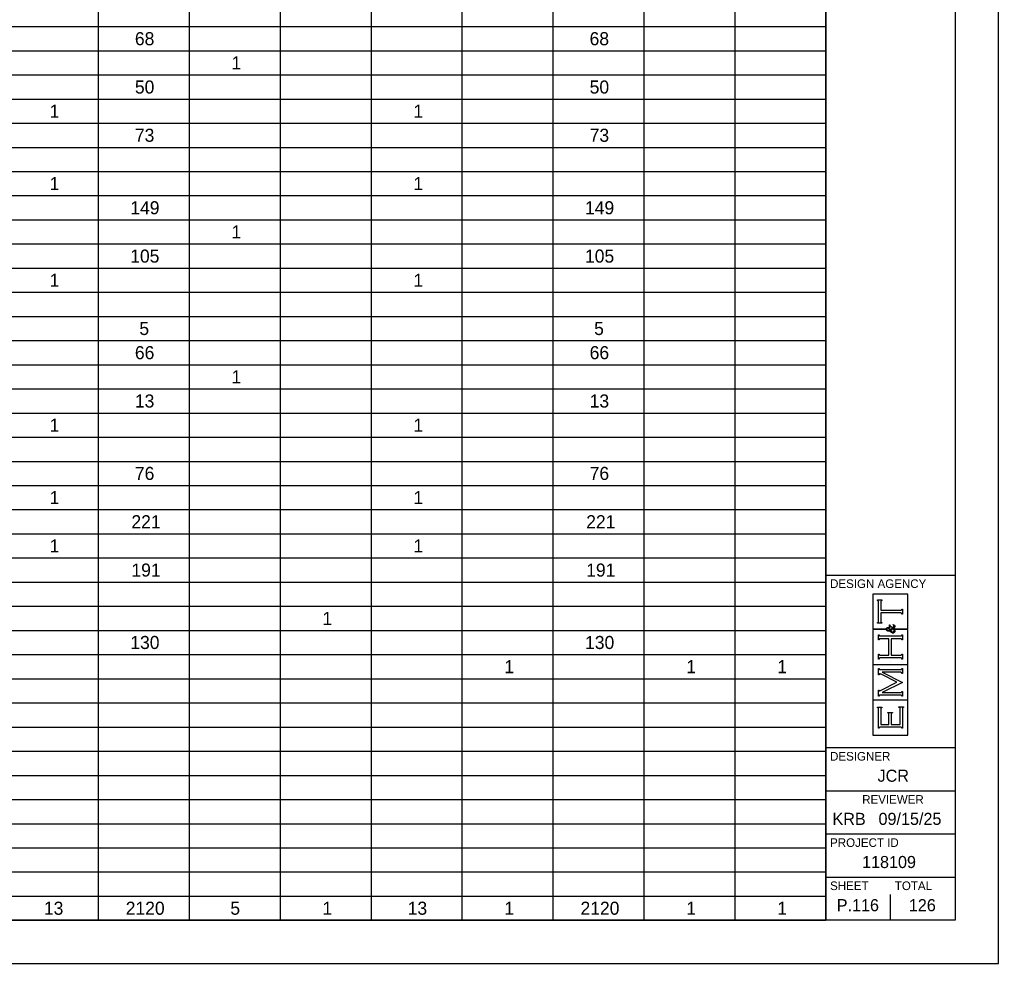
# Model space of a CAD drawing. Extents: x 0 to 34, y 0 to 22.
# Drawn here: x 22.66 to 34, y 0 to 10.94 of the extents above; entities that cross this region are included whole.
import ezdxf

# ---------------------------------------------------------------- set-up
doc = ezdxf.new("R2010")
doc.units = 0
for name, color, linetype in [('Default', 7, 'Continuous'), ('SH_Border', 7, 'Continuous'), ('SH_Cut_Line', 7, 'Continuous'), ('SH_Data', 7, 'Continuous')]:
    doc.layers.add(name, color=color, linetype=linetype)

msp = doc.modelspace()

# ---------------------------------------------------------------- linework, layer by layer
at = {"layer": 'Default'}
for p, q in [((23.571, 21.489), (23.571, 0.5)), ((24.625, 21.489), (24.625, 0.5)), ((25.679, 21.489), (25.679, 0.5)), ((26.732, 21.489), (26.732, 0.5)), ((27.786, 21.489), (27.786, 0.5)), ((28.839, 21.489), (28.839, 0.5)), ((29.893, 21.489), (29.893, 0.5)), ((30.946, 21.489), (30.946, 0.5)), ((32, 21.489), (32, 0.5)), ((1.496, 10.855), (32, 10.855)), ((1.496, 10.575), (32, 10.575)), ((1.496, 10.295), (32, 10.295)), ((1.496, 10.015), (32, 10.015)), ((1.496, 9.735), (32, 9.735)), ((1.496, 9.455), (32, 9.455)), ((1.496, 9.175), (32, 9.175)), ((1.496, 8.896), (32, 8.896)), ((1.496, 8.616), (32, 8.616)), ((1.496, 8.336), (32, 8.336)), ((1.496, 8.056), (32, 8.056)), ((1.496, 7.776), (32, 7.776)), ((1.496, 7.496), (32, 7.496)), ((1.496, 7.217), (32, 7.217)), ((1.496, 6.937), (32, 6.937)), ((1.496, 6.657), (32, 6.657)), ((1.496, 6.377), (32, 6.377)), ((1.496, 6.097), (32, 6.097)), ((1.496, 5.817), (32, 5.817)), ((1.496, 5.537), (32, 5.537)), ((1.496, 5.258), (32, 5.258)), ((1.496, 4.978), (32, 4.978)), ((1.496, 4.698), (32, 4.698)), ((1.496, 4.418), (32, 4.418)), ((1.496, 4.138), (32, 4.138)), ((1.496, 3.858), (32, 3.858)), ((1.496, 3.578), (32, 3.578)), ((1.496, 3.299), (32, 3.299)), ((1.496, 3.019), (32, 3.019)), ((1.496, 2.739), (32, 2.739)), ((1.496, 2.459), (32, 2.459)), ((1.496, 2.179), (32, 2.179)), ((1.496, 1.899), (32, 1.899)), ((1.496, 1.619), (32, 1.619)), ((1.496, 1.34), (32, 1.34)), ((1.496, 1.06), (32, 1.06)), ((1.496, 0.78), (32, 0.78)), ((1.496, 0.5), (32, 0.5))]:
    msp.add_line(p, q, dxfattribs=at)
at = {"layer": 'SH_Border'}
for p, q in [((32, 0.5), (32, 21.5)), ((32, 4.5), (33.5, 4.5)), ((32, 2.5), (33.5, 2.5)), ((32, 2), (33.5, 2)), ((32, 1.5), (33.5, 1.5)), ((32, 1), (33.5, 1))]:
    msp.add_line(p, q, dxfattribs=at)
msp.add_lwpolyline([(1.5, 21.5), (33.5, 21.5), (33.5, 0.5), (1.5, 0.5)], close=True, dxfattribs=at)
at = {"layer": 'SH_Cut_Line'}
msp.add_lwpolyline([(0, 0), (34, 0), (34, 22), (0, 22)], close=True, dxfattribs=at)
at = {"layer": 'SH_Data'}
for p, q in [((32.952, 4.279), (32.547, 4.279)), ((32.547, 4.279), (32.547, 3.875)), ((32.598, 4.204), (32.598, 4.211)), ((32.598, 4.211), (32.65, 4.211)), ((32.603, 4.203), (32.598, 4.204)), ((32.606, 4.201), (32.603, 4.203)), ((32.608, 4.199), (32.606, 4.201)), ((32.61, 4.196), (32.608, 4.199)), ((32.611, 4.192), (32.61, 4.196)), ((32.638, 4.196), (32.637, 4.192)), ((32.64, 4.199), (32.638, 4.196)), ((32.642, 4.201), (32.64, 4.199)), ((32.645, 4.203), (32.642, 4.201)), ((32.65, 4.204), (32.645, 4.203)), ((32.65, 4.211), (32.65, 4.204)), ((32.952, 3.875), (32.952, 4.279)), ((32.611, 4.187), (32.611, 4.192)), ((32.611, 3.968), (32.611, 4.187)), ((32.637, 4.192), (32.637, 4.187)), ((32.637, 4.187), (32.637, 4.093)), ((32.637, 4.093), (32.864, 4.093)), ((32.864, 4.093), (32.869, 4.093)), ((32.869, 4.093), (32.873, 4.094)), ((32.873, 4.094), (32.876, 4.096)), ((32.876, 4.096), (32.878, 4.097)), ((32.878, 4.097), (32.88, 4.101)), ((32.88, 4.101), (32.881, 4.106)), ((32.881, 4.106), (32.888, 4.106)), ((32.888, 4.106), (32.888, 4.048)), ((32.864, 4.061), (32.637, 4.061)), ((32.637, 4.061), (32.637, 3.968)), ((32.87, 4.061), (32.864, 4.061)), ((32.874, 4.06), (32.87, 4.061)), ((32.876, 4.059), (32.874, 4.06)), ((32.878, 4.057), (32.876, 4.059)), ((32.88, 4.053), (32.878, 4.057)), ((32.881, 4.048), (32.88, 4.053)), ((32.888, 4.048), (32.881, 4.048)), ((32.547, 3.875), (32.696, 3.875)), ((32.696, 3.869), (32.547, 3.869)), ((32.547, 3.869), (32.547, 3.465)), ((32.598, 3.95), (32.603, 3.951)), ((32.598, 3.944), (32.598, 3.95)), ((32.65, 3.944), (32.598, 3.944)), ((32.603, 3.951), (32.606, 3.953)), ((32.606, 3.953), (32.608, 3.955)), ((32.608, 3.955), (32.61, 3.958)), ((32.61, 3.958), (32.611, 3.962)), ((32.611, 3.962), (32.611, 3.968)), ((32.637, 3.968), (32.637, 3.962)), ((32.637, 3.962), (32.638, 3.958)), ((32.638, 3.958), (32.64, 3.955)), ((32.64, 3.955), (32.642, 3.953)), ((32.642, 3.953), (32.645, 3.951)), ((32.645, 3.951), (32.65, 3.95)), ((32.65, 3.95), (32.65, 3.944)), ((32.696, 3.875), (32.696, 3.869)), ((32.703, 3.879), (32.705, 3.883)), ((32.703, 3.873), (32.703, 3.879)), ((32.703, 3.868), (32.703, 3.873)), ((32.705, 3.863), (32.703, 3.868)), ((32.705, 3.883), (32.708, 3.887)), ((32.708, 3.858), (32.705, 3.863)), ((32.708, 3.887), (32.711, 3.89)), ((32.709, 3.879), (32.708, 3.876)), ((32.708, 3.876), (32.708, 3.873)), ((32.708, 3.873), (32.708, 3.869)), ((32.708, 3.869), (32.71, 3.866)), ((32.712, 3.853), (32.708, 3.858)), ((32.712, 3.881), (32.709, 3.879)), ((32.71, 3.866), (32.712, 3.864)), ((32.711, 3.89), (32.715, 3.892)), ((32.714, 3.883), (32.712, 3.881)), ((32.712, 3.864), (32.715, 3.862)), ((32.716, 3.884), (32.714, 3.883)), ((32.715, 3.892), (32.72, 3.892)), ((32.715, 3.862), (32.718, 3.861)), ((32.72, 3.884), (32.716, 3.884)), ((32.718, 3.861), (32.721, 3.861)), ((32.72, 3.892), (32.725, 3.892)), ((32.724, 3.884), (32.72, 3.884)), ((32.721, 3.861), (32.723, 3.861)), ((32.723, 3.861), (32.725, 3.862)), ((32.728, 3.882), (32.724, 3.884)), ((32.725, 3.892), (32.729, 3.89)), ((32.725, 3.862), (32.728, 3.862)), ((32.731, 3.88), (32.728, 3.882)), ((32.728, 3.862), (32.731, 3.863)), ((32.729, 3.89), (32.732, 3.887)), ((32.734, 3.877), (32.731, 3.88)), ((32.731, 3.863), (32.735, 3.865)), ((32.732, 3.887), (32.736, 3.883)), ((32.737, 3.872), (32.734, 3.877)), ((32.735, 3.865), (32.74, 3.867)), ((32.736, 3.883), (32.74, 3.878)), ((32.74, 3.867), (32.737, 3.872)), ((32.738, 3.893), (32.738, 3.922)), ((32.738, 3.922), (32.741, 3.922)), ((32.741, 3.893), (32.738, 3.893)), ((32.74, 3.878), (32.744, 3.869)), ((32.741, 3.922), (32.741, 3.918)), ((32.741, 3.918), (32.742, 3.915)), ((32.742, 3.896), (32.741, 3.895)), ((32.741, 3.895), (32.741, 3.893)), ((32.742, 3.915), (32.743, 3.913)), ((32.743, 3.897), (32.742, 3.896)), ((32.743, 3.913), (32.745, 3.911)), ((32.745, 3.899), (32.743, 3.897)), ((32.744, 3.869), (32.754, 3.875)), ((32.745, 3.911), (32.749, 3.908)), ((32.746, 3.899), (32.745, 3.899)), ((32.748, 3.899), (32.746, 3.899)), ((32.755, 3.899), (32.748, 3.899)), ((32.749, 3.908), (32.756, 3.904)), ((32.756, 3.86), (32.751, 3.857)), ((32.751, 3.857), (32.754, 3.852)), ((32.754, 3.875), (32.764, 3.881)), ((32.763, 3.895), (32.755, 3.899)), ((32.756, 3.904), (32.763, 3.9)), ((32.761, 3.863), (32.756, 3.86)), ((32.764, 3.865), (32.761, 3.863)), ((32.763, 3.9), (32.77, 3.896)), ((32.772, 3.887), (32.763, 3.895)), ((32.764, 3.881), (32.772, 3.887)), ((32.768, 3.867), (32.764, 3.865)), ((32.774, 3.872), (32.768, 3.867)), ((32.77, 3.896), (32.776, 3.891)), ((32.782, 3.878), (32.774, 3.872)), ((32.776, 3.891), (32.781, 3.895)), ((32.779, 3.923), (32.781, 3.926)), ((32.782, 3.922), (32.779, 3.923)), ((32.781, 3.926), (32.787, 3.924)), ((32.781, 3.895), (32.784, 3.898)), ((32.785, 3.921), (32.782, 3.922)), ((32.786, 3.873), (32.782, 3.878)), ((32.784, 3.898), (32.786, 3.901)), ((32.786, 3.919), (32.785, 3.921)), ((32.788, 3.917), (32.786, 3.919)), ((32.786, 3.901), (32.788, 3.904)), ((32.791, 3.886), (32.786, 3.881)), ((32.786, 3.881), (32.791, 3.876)), ((32.788, 3.869), (32.786, 3.873)), ((32.787, 3.924), (32.792, 3.921)), ((32.789, 3.914), (32.788, 3.917)), ((32.788, 3.904), (32.789, 3.908)), ((32.79, 3.867), (32.788, 3.869)), ((32.789, 3.911), (32.789, 3.914)), ((32.789, 3.908), (32.789, 3.911)), ((32.791, 3.864), (32.79, 3.867)), ((32.794, 3.89), (32.791, 3.886)), ((32.791, 3.876), (32.795, 3.87)), ((32.791, 3.861), (32.791, 3.864)), ((32.791, 3.859), (32.791, 3.861)), ((32.791, 3.853), (32.791, 3.859)), ((32.792, 3.921), (32.795, 3.918)), ((32.796, 3.894), (32.794, 3.89)), ((32.795, 3.918), (32.798, 3.914)), ((32.795, 3.87), (32.797, 3.866)), ((32.798, 3.897), (32.796, 3.894)), ((32.797, 3.866), (32.798, 3.861)), ((32.798, 3.914), (32.799, 3.91)), ((32.799, 3.901), (32.798, 3.897)), ((32.798, 3.861), (32.799, 3.857)), ((32.799, 3.91), (32.799, 3.905)), ((32.799, 3.905), (32.799, 3.901)), ((32.803, 3.869), (32.799, 3.875)), ((32.799, 3.875), (32.952, 3.875)), ((32.799, 3.857), (32.799, 3.852)), ((32.952, 3.869), (32.803, 3.869)), ((32.952, 3.465), (32.952, 3.869)), ((32.611, 3.749), (32.611, 3.807)), ((32.611, 3.807), (32.617, 3.807)), ((32.617, 3.749), (32.611, 3.749)), ((32.617, 3.807), (32.619, 3.802)), ((32.618, 3.754), (32.617, 3.749)), ((32.62, 3.758), (32.618, 3.754)), ((32.619, 3.802), (32.62, 3.798)), ((32.62, 3.798), (32.623, 3.797)), ((32.623, 3.76), (32.62, 3.758)), ((32.623, 3.797), (32.625, 3.795)), ((32.625, 3.761), (32.623, 3.76)), ((32.625, 3.795), (32.629, 3.794)), ((32.629, 3.762), (32.625, 3.761)), ((32.629, 3.794), (32.635, 3.794)), ((32.635, 3.762), (32.629, 3.762)), ((32.635, 3.794), (32.864, 3.794)), ((32.732, 3.762), (32.635, 3.762)), ((32.718, 3.85), (32.712, 3.853)), ((32.726, 3.85), (32.718, 3.85)), ((32.729, 3.85), (32.726, 3.85)), ((32.731, 3.85), (32.729, 3.85)), ((32.734, 3.851), (32.731, 3.85)), ((32.732, 3.572), (32.732, 3.762)), ((32.737, 3.852), (32.734, 3.851)), ((32.741, 3.853), (32.737, 3.852)), ((32.746, 3.855), (32.741, 3.853)), ((32.752, 3.844), (32.746, 3.855)), ((32.757, 3.837), (32.752, 3.844)), ((32.754, 3.852), (32.757, 3.848)), ((32.757, 3.848), (32.761, 3.845)), ((32.763, 3.833), (32.757, 3.837)), ((32.864, 3.762), (32.759, 3.762)), ((32.759, 3.762), (32.759, 3.572)), ((32.761, 3.845), (32.765, 3.843)), ((32.768, 3.829), (32.763, 3.833)), ((32.765, 3.843), (32.769, 3.841)), ((32.774, 3.827), (32.768, 3.829)), ((32.769, 3.841), (32.773, 3.841)), ((32.773, 3.841), (32.778, 3.841)), ((32.779, 3.827), (32.774, 3.827)), ((32.778, 3.841), (32.782, 3.843)), ((32.785, 3.827), (32.779, 3.827)), ((32.782, 3.843), (32.786, 3.846)), ((32.79, 3.829), (32.785, 3.827)), ((32.786, 3.846), (32.789, 3.849)), ((32.789, 3.849), (32.791, 3.853)), ((32.793, 3.834), (32.79, 3.829)), ((32.797, 3.838), (32.793, 3.834)), ((32.799, 3.844), (32.797, 3.838)), ((32.799, 3.852), (32.799, 3.844)), ((32.864, 3.794), (32.869, 3.794)), ((32.87, 3.762), (32.864, 3.762)), ((32.869, 3.794), (32.873, 3.795)), ((32.874, 3.761), (32.87, 3.762)), ((32.873, 3.795), (32.876, 3.797)), ((32.876, 3.76), (32.874, 3.761)), ((32.876, 3.797), (32.878, 3.798)), ((32.878, 3.758), (32.876, 3.76)), ((32.878, 3.798), (32.88, 3.802)), ((32.88, 3.754), (32.878, 3.758)), ((32.88, 3.802), (32.881, 3.807)), ((32.881, 3.749), (32.88, 3.754)), ((32.881, 3.807), (32.888, 3.807)), ((32.888, 3.749), (32.881, 3.749)), ((32.888, 3.807), (32.888, 3.749)), ((32.611, 3.527), (32.611, 3.585)), ((32.611, 3.585), (32.617, 3.585)), ((32.617, 3.527), (32.611, 3.527)), ((32.617, 3.585), (32.619, 3.58)), ((32.618, 3.532), (32.617, 3.527)), ((32.62, 3.536), (32.618, 3.532)), ((32.619, 3.58), (32.62, 3.576)), ((32.62, 3.576), (32.623, 3.574)), ((32.623, 3.537), (32.62, 3.536)), ((32.623, 3.574), (32.625, 3.573)), ((32.625, 3.539), (32.623, 3.537)), ((32.625, 3.573), (32.629, 3.572)), ((32.629, 3.54), (32.625, 3.539)), ((32.629, 3.572), (32.635, 3.572)), ((32.635, 3.54), (32.629, 3.54)), ((32.635, 3.572), (32.732, 3.572)), ((32.864, 3.54), (32.635, 3.54)), ((32.759, 3.572), (32.864, 3.572)), ((32.864, 3.572), (32.87, 3.572)), ((32.87, 3.54), (32.864, 3.54)), ((32.87, 3.572), (32.874, 3.573)), ((32.874, 3.539), (32.87, 3.54)), ((32.874, 3.573), (32.876, 3.574)), ((32.876, 3.538), (32.874, 3.539)), ((32.876, 3.574), (32.878, 3.576)), ((32.878, 3.536), (32.876, 3.538)), ((32.878, 3.576), (32.88, 3.58)), ((32.88, 3.532), (32.878, 3.536)), ((32.88, 3.58), (32.881, 3.585)), ((32.881, 3.527), (32.88, 3.532)), ((32.881, 3.585), (32.888, 3.585)), ((32.888, 3.527), (32.881, 3.527)), ((32.888, 3.585), (32.888, 3.527)), ((32.547, 3.465), (32.952, 3.465)), ((32.952, 3.459), (32.547, 3.459)), ((32.547, 3.459), (32.547, 3.055)), ((32.611, 3.345), (32.611, 3.418)), ((32.611, 3.418), (32.617, 3.418)), ((32.617, 3.418), (32.619, 3.412)), ((32.619, 3.412), (32.62, 3.409)), ((32.62, 3.409), (32.623, 3.407)), ((32.623, 3.407), (32.625, 3.405)), ((32.625, 3.405), (32.629, 3.405)), ((32.629, 3.405), (32.635, 3.405)), ((32.635, 3.405), (32.864, 3.405)), ((32.75, 3.5), (32.75, 3.5)), ((32.864, 3.405), (32.869, 3.405)), ((32.869, 3.405), (32.873, 3.405)), ((32.873, 3.405), (32.876, 3.407)), ((32.876, 3.407), (32.878, 3.409)), ((32.878, 3.409), (32.88, 3.412)), ((32.88, 3.412), (32.881, 3.418)), ((32.881, 3.418), (32.888, 3.418)), ((32.888, 3.418), (32.888, 3.36)), ((32.952, 3.055), (32.952, 3.459)), ((32.617, 3.345), (32.611, 3.345)), ((32.62, 3.352), (32.617, 3.345)), ((32.622, 3.355), (32.62, 3.352)), ((32.626, 3.355), (32.622, 3.355)), ((32.629, 3.355), (32.626, 3.355)), ((32.633, 3.353), (32.629, 3.355)), ((32.64, 3.35), (32.633, 3.353)), ((32.825, 3.257), (32.64, 3.35)), ((32.864, 3.373), (32.654, 3.373)), ((32.654, 3.373), (32.888, 3.255)), ((32.87, 3.373), (32.864, 3.373)), ((32.874, 3.372), (32.87, 3.373)), ((32.876, 3.37), (32.874, 3.372)), ((32.878, 3.369), (32.876, 3.37)), ((32.88, 3.365), (32.878, 3.369)), ((32.881, 3.36), (32.88, 3.365)), ((32.888, 3.36), (32.881, 3.36)), ((32.641, 3.165), (32.825, 3.257)), ((32.888, 3.255), (32.654, 3.138)), ((32.611, 3.096), (32.611, 3.168)), ((32.611, 3.168), (32.617, 3.168)), ((32.617, 3.096), (32.611, 3.096)), ((32.617, 3.168), (32.62, 3.162)), ((32.618, 3.102), (32.617, 3.096)), ((32.62, 3.105), (32.618, 3.102)), ((32.62, 3.162), (32.622, 3.158)), ((32.623, 3.107), (32.62, 3.105)), ((32.622, 3.158), (32.626, 3.158)), ((32.625, 3.109), (32.623, 3.107)), ((32.629, 3.109), (32.625, 3.109)), ((32.626, 3.158), (32.627, 3.158)), ((32.627, 3.158), (32.633, 3.161)), ((32.635, 3.109), (32.629, 3.109)), ((32.633, 3.161), (32.641, 3.165)), ((32.864, 3.109), (32.635, 3.109)), ((32.654, 3.138), (32.864, 3.138)), ((32.864, 3.138), (32.869, 3.138)), ((32.87, 3.109), (32.864, 3.109)), ((32.869, 3.138), (32.873, 3.139)), ((32.874, 3.109), (32.87, 3.109)), ((32.873, 3.139), (32.876, 3.141)), ((32.876, 3.107), (32.874, 3.109)), ((32.876, 3.141), (32.878, 3.143)), ((32.878, 3.105), (32.876, 3.107)), ((32.878, 3.143), (32.88, 3.146)), ((32.88, 3.102), (32.878, 3.105)), ((32.88, 3.146), (32.881, 3.151)), ((32.881, 3.096), (32.88, 3.102)), ((32.881, 3.151), (32.888, 3.151)), ((32.888, 3.096), (32.881, 3.096)), ((32.888, 3.151), (32.888, 3.096)), ((32.547, 3.055), (32.952, 3.055)), ((32.952, 3.049), (32.547, 3.049)), ((32.547, 3.049), (32.547, 2.645)), ((32.598, 2.962), (32.598, 2.969)), ((32.598, 2.969), (32.65, 2.969)), ((32.603, 2.961), (32.598, 2.962)), ((32.606, 2.959), (32.603, 2.961)), ((32.608, 2.957), (32.606, 2.959)), ((32.61, 2.955), (32.608, 2.957)), ((32.611, 2.951), (32.61, 2.955)), ((32.611, 2.945), (32.611, 2.951)), ((32.64, 2.957), (32.638, 2.955)), ((32.638, 2.955), (32.638, 2.951)), ((32.638, 2.951), (32.638, 2.945)), ((32.642, 2.959), (32.64, 2.957)), ((32.645, 2.961), (32.642, 2.959)), ((32.65, 2.962), (32.645, 2.961)), ((32.65, 2.969), (32.65, 2.962)), ((32.848, 2.965), (32.848, 2.972)), ((32.848, 2.972), (32.901, 2.972)), ((32.853, 2.964), (32.848, 2.965)), ((32.857, 2.962), (32.853, 2.964)), ((32.859, 2.96), (32.857, 2.962)), ((32.86, 2.958), (32.859, 2.96)), ((32.861, 2.953), (32.86, 2.958)), ((32.861, 2.948), (32.861, 2.953)), ((32.889, 2.957), (32.888, 2.953)), ((32.888, 2.953), (32.888, 2.948)), ((32.891, 2.96), (32.889, 2.957)), ((32.892, 2.962), (32.891, 2.96)), ((32.896, 2.964), (32.892, 2.962)), ((32.901, 2.965), (32.896, 2.964)), ((32.901, 2.972), (32.901, 2.965)), ((32.952, 2.645), (32.952, 3.049)), ((32.611, 2.725), (32.611, 2.945)), ((32.638, 2.945), (32.638, 2.77)), ((32.719, 2.902), (32.719, 2.908)), ((32.719, 2.908), (32.772, 2.908)), ((32.724, 2.901), (32.719, 2.902)), ((32.728, 2.899), (32.724, 2.901)), ((32.729, 2.896), (32.728, 2.899)), ((32.731, 2.894), (32.729, 2.896)), ((32.732, 2.89), (32.731, 2.894)), ((32.732, 2.884), (32.732, 2.89)), ((32.732, 2.77), (32.732, 2.884)), ((32.76, 2.894), (32.759, 2.89)), ((32.759, 2.89), (32.759, 2.884)), ((32.759, 2.884), (32.759, 2.77)), ((32.761, 2.896), (32.76, 2.894)), ((32.763, 2.899), (32.761, 2.896)), ((32.767, 2.901), (32.763, 2.899)), ((32.772, 2.902), (32.767, 2.901)), ((32.772, 2.908), (32.772, 2.902)), ((32.861, 2.77), (32.861, 2.948)), ((32.888, 2.948), (32.888, 2.725)), ((32.617, 2.725), (32.611, 2.725)), ((32.619, 2.73), (32.617, 2.725)), ((32.62, 2.734), (32.619, 2.73)), ((32.623, 2.735), (32.62, 2.734)), ((32.625, 2.737), (32.623, 2.735)), ((32.629, 2.738), (32.625, 2.737)), ((32.635, 2.738), (32.629, 2.738)), ((32.864, 2.738), (32.635, 2.738)), ((32.638, 2.77), (32.732, 2.77)), ((32.759, 2.77), (32.861, 2.77)), ((32.87, 2.738), (32.864, 2.738)), ((32.874, 2.737), (32.87, 2.738)), ((32.876, 2.735), (32.874, 2.737)), ((32.878, 2.734), (32.876, 2.735)), ((32.88, 2.73), (32.878, 2.734)), ((32.881, 2.725), (32.88, 2.73)), ((32.888, 2.725), (32.881, 2.725)), ((32.547, 2.645), (32.952, 2.645)), ((32.75, 0.5), (32.75, 0.8)), ((32.375, 0.675), (32.375, 0.675))]:
    msp.add_line(p, q, dxfattribs=at)

# ---------------------------------------------------------------- texts
at = {"layer": 'Default'}
for s, height, p in [('68', 0.1515, (23.997, 10.639)), ('68', 0.1515, (29.264, 10.639)), ('1', 0.151, (25.116, 10.359)), ('50', 0.1515, (23.997, 10.079)), ('50', 0.1515, (29.265, 10.079)), ('1', 0.151, (23.009, 9.799)), ('1', 0.151, (27.224, 9.799)), ('73', 0.1515, (23.997, 9.52)), ('73', 0.1515, (29.265, 9.52)), ('1', 0.151, (23.009, 8.96)), ('1', 0.151, (27.224, 8.96)), ('149', 0.1515, (23.944, 8.68)), ('149', 0.1515, (29.211, 8.68)), ('1', 0.151, (25.116, 8.4)), ('105', 0.1515, (23.943, 8.12)), ('105', 0.1515, (29.211, 8.12)), ('1', 0.151, (23.009, 7.84)), ('1', 0.151, (27.224, 7.84)), ('5', 0.151, (24.049, 7.281)), ('5', 0.151, (29.317, 7.281)), ('66', 0.1515, (23.997, 7.001)), ('66', 0.1515, (29.265, 7.001)), ('1', 0.151, (25.116, 6.721)), ('13', 0.1515, (23.997, 6.441)), ('13', 0.1515, (29.265, 6.441)), ('1', 0.151, (23.009, 6.161)), ('1', 0.151, (27.224, 6.161)), ('76', 0.1515, (23.997, 5.602)), ('76', 0.1515, (29.265, 5.602)), ('1', 0.151, (23.009, 5.322)), ('1', 0.151, (27.224, 5.322)), ('221', 0.1515, (23.957, 5.042)), ('221', 0.1515, (29.225, 5.042)), ('1', 0.151, (23.009, 4.762)), ('1', 0.151, (27.224, 4.762)), ('191', 0.1515, (23.957, 4.482)), ('191', 0.1515, (29.225, 4.482)), ('1', 0.151, (26.17, 3.922)), ('130', 0.1515, (23.944, 3.643)), ('130', 0.1515, (29.212, 3.643)), ('1', 0.151, (28.277, 3.363)), ('1', 0.151, (30.384, 3.363)), ('1', 0.151, (31.438, 3.363)), ('13', 0.1515, (22.943, 0.564)), ('2120', 0.1515, (23.891, 0.564)), ('5', 0.151, (25.103, 0.564)), ('1', 0.151, (26.17, 0.564)), ('13', 0.1515, (27.157, 0.564)), ('1', 0.151, (28.277, 0.564)), ('2120', 0.1515, (29.159, 0.564)), ('1', 0.151, (30.384, 0.564)), ('1', 0.151, (31.438, 0.564))]:
    msp.add_text(s, height=height, dxfattribs=at).set_placement(p)
at = {"layer": 'SH_Data'}
for s, height, p in [('DESIGN AGENCY', 0.1, (32.05, 4.35)), ('DESIGNER', 0.1, (32.05, 2.35)), ('JCR', 0.14, (32.6, 2.105)), ('REVIEWER', 0.1, (32.422, 1.85)), ('KRB', 0.14, (32.078, 1.605)), ('09/15/25', 0.14, (32.611, 1.605)), ('PROJECT ID', 0.1, (32.05, 1.35)), ('118109', 0.14, (32.42, 1.105)), ('SHEET', 0.1, (32.05, 0.85)), ('TOTAL', 0.1, (32.8, 0.85)), ('P.116', 0.14, (32.127, 0.605)), ('126', 0.14, (32.962, 0.605))]:
    msp.add_text(s, height=height, dxfattribs=at).set_placement(p)

doc.saveas('drawing.dxf')
